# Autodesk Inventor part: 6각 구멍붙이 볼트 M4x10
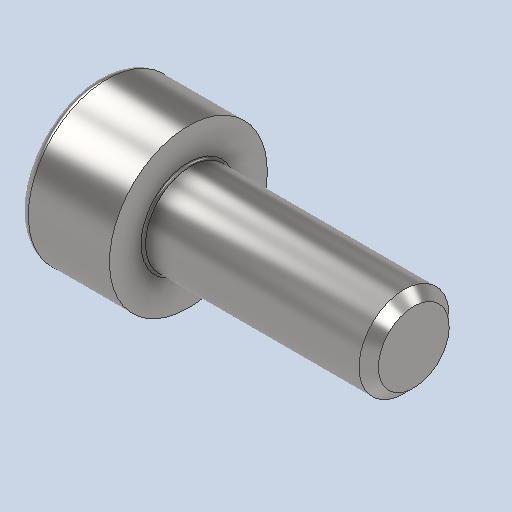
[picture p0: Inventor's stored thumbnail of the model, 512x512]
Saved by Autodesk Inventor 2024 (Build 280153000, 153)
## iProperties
Created: 2026-07
Part Number: 6각 구멍붙이 볼트 M4x10
Material: 강철, 연강
Description: 6각머리 태핑 나사
Document SubType Name: Modeling
Designer: com
Density: 7.86 g/cm^3
Appearance: 기본값
Author: jhkim
Revision Number: 1
Sending System: Autodesk Inventor 2027
Preprocessor: ST-DEVELOPER v20.1
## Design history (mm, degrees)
node "6각 구멍붙이 볼트 M4x101"
node "솔리드1"
body "Solid1"
